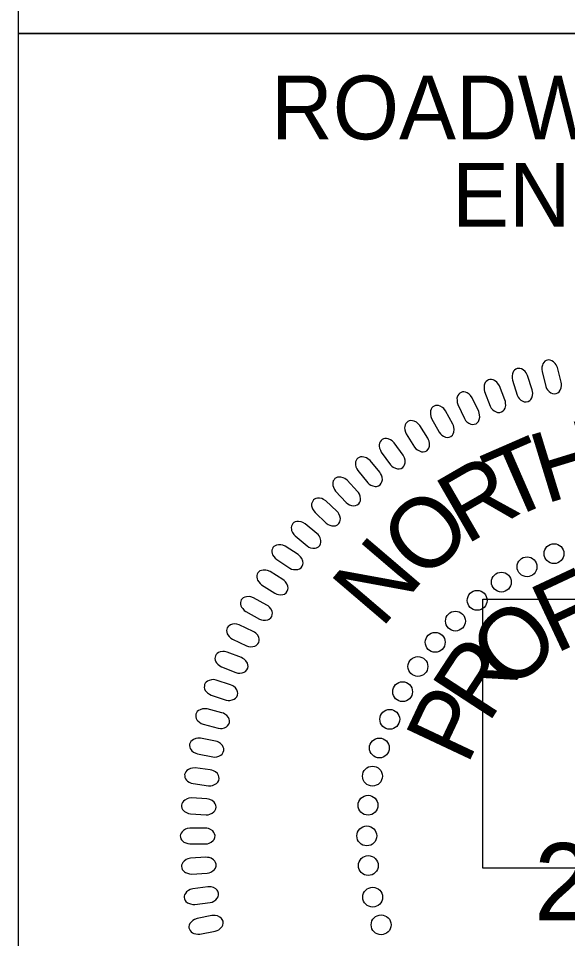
# Model space of a CAD drawing. Extents: x 18938 to 19565, y 6931 to 7973.
# Drawn here: x 19353.14 to 19358.89, y 7208.36 to 7218.01 of the extents above; entities that cross this region are included whole.
import ezdxf

# ---------------------------------------------------------------- set-up
doc = ezdxf.new("R2010")
doc.units = 0
for name, color, linetype in [('Old_Level_10', 7, 'Continuous'), ('Prop Pavement Schedule Description CELL', 7, 'Continuous'), ('Scratch_Level_5', 7, 'Continuous'), ('Typical Pavement Slope Information CELL', 7, 'Continuous')]:
    doc.layers.add(name, color=color, linetype=linetype)

# ---------------------------------------------------------------- blocks, each defined once
blk = doc.blocks.new('Brandon J. McInnis')
at = {"layer": 'Old_Level_10'}
for points in [[(-60.071, 87.604), (-60.375, 88.792), (-60.466, 88.995), (-60.552, 89.118), (-60.702, 89.254), (-60.824, 89.336), (-60.952, 89.386), (-61.064, 89.399), (-61.177, 89.39), (-61.281, 89.343), (-61.389, 89.284), (-61.476, 89.2), (-61.552, 89.077), (-61.591, 88.986), (-61.619, 88.823), (-61.632, 88.635), (-61.614, 88.475), (-61.309, 87.256), (-61.245, 87.097), (-61.167, 86.973), (-61.04, 86.841), (-60.897, 86.733), (-60.783, 86.681), (-60.616, 86.661), (-60.466, 86.679), (-60.331, 86.754), (-60.243, 86.829), (-60.144, 86.957), (-60.071, 87.151), (-60.05, 87.342), (-60.053, 87.474)], [(-62.405, 86.983), (-62.783, 88.15), (-62.886, 88.347), (-62.979, 88.464), (-63.138, 88.591), (-63.264, 88.665), (-63.396, 88.706), (-63.508, 88.712), (-63.62, 88.696), (-63.721, 88.643), (-63.825, 88.577), (-63.906, 88.489), (-63.975, 88.361), (-64.008, 88.266), (-64.026, 88.103), (-64.027, 87.914), (-63.999, 87.755), (-63.618, 86.558), (-63.544, 86.404), (-63.459, 86.285), (-63.324, 86.161), (-63.175, 86.063), (-63.058, 86.017), (-62.889, 86.008), (-62.741, 86.035), (-62.611, 86.119), (-62.527, 86.199), (-62.437, 86.333), (-62.376, 86.532), (-62.367, 86.723), (-62.379, 86.856)], [(-64.605, 86.167), (-65.057, 87.308), (-65.172, 87.498), (-65.272, 87.609), (-65.439, 87.725), (-65.569, 87.791), (-65.703, 87.824), (-65.815, 87.823), (-65.926, 87.8), (-66.023, 87.74), (-66.124, 87.668), (-66.199, 87.574), (-66.26, 87.443), (-66.286, 87.347), (-66.294, 87.183), (-66.283, 86.994), (-66.245, 86.838), (-65.79, 85.666), (-65.707, 85.517), (-65.614, 85.404), (-65.471, 85.288), (-65.316, 85.2), (-65.196, 85.161), (-65.028, 85.163), (-64.882, 85.2), (-64.758, 85.292), (-64.679, 85.377), (-64.597, 85.516), (-64.548, 85.718), (-64.552, 85.91), (-64.572, 86.041)], [(-66.723, 85.234), (-67.245, 86.344), (-67.372, 86.526), (-67.479, 86.631), (-67.652, 86.737), (-67.787, 86.794), (-67.922, 86.819), (-68.034, 86.811), (-68.144, 86.781), (-68.237, 86.715), (-68.332, 86.638), (-68.402, 86.539), (-68.454, 86.404), (-68.474, 86.306), (-68.472, 86.142), (-68.449, 85.954), (-68.402, 85.8), (-67.873, 84.661), (-67.781, 84.516), (-67.681, 84.409), (-67.532, 84.303), (-67.371, 84.224), (-67.25, 84.193), (-67.082, 84.206), (-66.938, 84.251), (-66.82, 84.351), (-66.746, 84.441), (-66.674, 84.585), (-66.637, 84.789), (-66.653, 84.98), (-66.681, 85.111)], [(-68.806, 84.22), (-69.397, 85.295), (-69.535, 85.47), (-69.648, 85.567), (-69.828, 85.662), (-69.966, 85.711), (-70.102, 85.727), (-70.213, 85.711), (-70.321, 85.675), (-70.41, 85.604), (-70.501, 85.52), (-70.563, 85.417), (-70.607, 85.279), (-70.621, 85.18), (-70.608, 85.017), (-70.574, 84.83), (-70.517, 84.68), (-69.918, 83.575), (-69.817, 83.437), (-69.71, 83.337), (-69.556, 83.24), (-69.389, 83.171), (-69.266, 83.148), (-69.099, 83.171), (-68.959, 83.226), (-68.847, 83.333), (-68.779, 83.427), (-68.716, 83.576), (-68.693, 83.782), (-68.72, 83.972), (-68.757, 84.099)], [(-70.823, 83.078), (-71.48, 84.114), (-71.63, 84.28), (-71.748, 84.369), (-71.933, 84.453), (-72.074, 84.493), (-72.211, 84.5), (-72.322, 84.478), (-72.427, 84.435), (-72.511, 84.358), (-72.596, 84.269), (-72.652, 84.162), (-72.687, 84.022), (-72.695, 83.923), (-72.672, 83.76), (-72.626, 83.577), (-72.56, 83.429), (-71.893, 82.364), (-71.783, 82.233), (-71.67, 82.139), (-71.509, 82.053), (-71.34, 81.995), (-71.215, 81.979), (-71.05, 82.013), (-70.914, 82.076), (-70.809, 82.19), (-70.747, 82.288), (-70.693, 82.44), (-70.683, 82.648), (-70.723, 82.836), (-70.766, 82.96)], [(-72.824, 81.723), (-73.545, 82.716), (-73.704, 82.872), (-73.828, 82.954), (-74.019, 83.026), (-74.162, 83.057), (-74.299, 83.056), (-74.408, 83.027), (-74.51, 82.977), (-74.589, 82.895), (-74.668, 82.801), (-74.717, 82.691), (-74.744, 82.548), (-74.745, 82.449), (-74.712, 82.288), (-74.655, 82.107), (-74.579, 81.965), (-73.847, 80.944), (-73.729, 80.82), (-73.611, 80.733), (-73.445, 80.657), (-73.272, 80.61), (-73.146, 80.602), (-72.984, 80.646), (-72.851, 80.718), (-72.754, 80.838), (-72.699, 80.939), (-72.654, 81.095), (-72.657, 81.303), (-72.708, 81.488), (-72.76, 81.61)], [(-74.704, 80.335), (-75.486, 81.28), (-75.655, 81.425), (-75.784, 81.5), (-75.978, 81.559), (-76.123, 81.582), (-76.26, 81.572), (-76.366, 81.535), (-76.465, 81.479), (-76.539, 81.392), (-76.612, 81.293), (-76.655, 81.181), (-76.672, 81.037), (-76.667, 80.937), (-76.624, 80.779), (-76.556, 80.603), (-76.471, 80.465), (-75.677, 79.492), (-75.551, 79.376), (-75.427, 79.297), (-75.257, 79.231), (-75.081, 79.195), (-74.955, 79.195), (-74.796, 79.249), (-74.668, 79.329), (-74.579, 79.455), (-74.53, 79.56), (-74.495, 79.718), (-74.512, 79.925), (-74.574, 80.106), (-74.634, 80.225)], [(-76.492, 78.795), (-77.331, 79.69), (-77.509, 79.825), (-77.643, 79.891), (-77.841, 79.938), (-77.986, 79.951), (-78.123, 79.933), (-78.226, 79.89), (-78.322, 79.828), (-78.39, 79.736), (-78.457, 79.632), (-78.492, 79.518), (-78.5, 79.373), (-78.489, 79.274), (-78.436, 79.119), (-78.356, 78.947), (-78.264, 78.816), (-77.409, 77.894), (-77.277, 77.786), (-77.149, 77.715), (-76.974, 77.66), (-76.796, 77.634), (-76.671, 77.642), (-76.516, 77.707), (-76.393, 77.795), (-76.312, 77.926), (-76.269, 78.034), (-76.244, 78.193), (-76.273, 78.399), (-76.348, 78.576), (-76.414, 78.691)], [(-78.154, 77.186), (-79.048, 78.026), (-79.234, 78.149), (-79.371, 78.207), (-79.572, 78.241), (-79.718, 78.246), (-79.853, 78.218), (-79.954, 78.169), (-80.045, 78.101), (-80.107, 78.006), (-80.167, 77.898), (-80.196, 77.782), (-80.195, 77.637), (-80.177, 77.538), (-80.115, 77.387), (-80.025, 77.22), (-79.924, 77.094), (-79.013, 76.229), (-78.874, 76.129), (-78.742, 76.066), (-78.564, 76.022), (-78.386, 76.009), (-78.261, 76.024), (-78.11, 76.098), (-77.993, 76.193), (-77.92, 76.33), (-77.884, 76.44), (-77.87, 76.601), (-77.911, 76.804), (-77.996, 76.976), (-78.07, 77.086)], [(-79.768, 75.399), (-80.712, 76.182), (-80.906, 76.293), (-81.046, 76.342), (-81.249, 76.363), (-81.395, 76.358), (-81.527, 76.323), (-81.625, 76.268), (-81.712, 76.194), (-81.768, 76.095), (-81.821, 75.983), (-81.843, 75.865), (-81.832, 75.721), (-81.809, 75.624), (-81.736, 75.477), (-81.636, 75.315), (-81.528, 75.197), (-80.565, 74.39), (-80.42, 74.299), (-80.284, 74.245), (-80.103, 74.212), (-79.925, 74.209), (-79.801, 74.234), (-79.655, 74.316), (-79.544, 74.418), (-79.479, 74.559), (-79.451, 74.671), (-79.447, 74.833), (-79.501, 75.033), (-79.596, 75.2), (-79.678, 75.305)], [(-81.292, 73.697), (-82.322, 74.363), (-82.527, 74.45), (-82.673, 74.483), (-82.876, 74.48), (-83.021, 74.458), (-83.148, 74.407), (-83.239, 74.341), (-83.317, 74.257), (-83.361, 74.153), (-83.4, 74.036), (-83.407, 73.916), (-83.38, 73.774), (-83.346, 73.68), (-83.256, 73.542), (-83.138, 73.394), (-83.016, 73.289), (-81.965, 72.601), (-81.81, 72.528), (-81.669, 72.49), (-81.486, 72.478), (-81.308, 72.497), (-81.188, 72.536), (-81.053, 72.635), (-80.955, 72.749), (-80.907, 72.897), (-80.892, 73.011), (-80.907, 73.172), (-80.984, 73.365), (-81.099, 73.519), (-81.192, 73.614)], [(-82.507, 71.674), (-83.542, 72.332), (-83.747, 72.418), (-83.893, 72.449), (-84.097, 72.446), (-84.241, 72.422), (-84.369, 72.37), (-84.458, 72.303), (-84.536, 72.219), (-84.579, 72.113), (-84.617, 71.997), (-84.623, 71.876), (-84.595, 71.735), (-84.56, 71.641), (-84.469, 71.504), (-84.35, 71.357), (-84.228, 71.253), (-83.17, 70.573), (-83.015, 70.501), (-82.873, 70.464), (-82.691, 70.454), (-82.513, 70.474), (-82.393, 70.513), (-82.259, 70.614), (-82.162, 70.73), (-82.115, 70.877), (-82.101, 70.992), (-82.117, 71.153), (-82.196, 71.344), (-82.312, 71.497), (-82.405, 71.593)], [(-83.81, 69.625), (-84.885, 70.217), (-85.095, 70.29), (-85.243, 70.311), (-85.445, 70.295), (-85.589, 70.262), (-85.712, 70.203), (-85.797, 70.13), (-85.869, 70.042), (-85.905, 69.934), (-85.937, 69.815), (-85.935, 69.694), (-85.898, 69.554), (-85.857, 69.464), (-85.759, 69.332), (-85.63, 69.193), (-85.501, 69.097), (-84.404, 68.485), (-84.245, 68.422), (-84.101, 68.395), (-83.918, 68.396), (-83.741, 68.427), (-83.624, 68.474), (-83.496, 68.582), (-83.407, 68.704), (-83.37, 68.854), (-83.363, 68.969), (-83.389, 69.129), (-83.48, 69.315), (-83.605, 69.461), (-83.704, 69.55)], [(-84.919, 67.501), (-86.029, 68.024), (-86.243, 68.084), (-86.392, 68.096), (-86.593, 68.067), (-86.734, 68.026), (-86.853, 67.958), (-86.934, 67.88), (-87, 67.787), (-87.03, 67.678), (-87.053, 67.556), (-87.044, 67.437), (-86.999, 67.3), (-86.952, 67.212), (-86.845, 67.087), (-86.708, 66.956), (-86.574, 66.867), (-85.439, 66.325), (-85.277, 66.274), (-85.131, 66.255), (-84.949, 66.268), (-84.775, 66.31), (-84.661, 66.364), (-84.54, 66.48), (-84.458, 66.607), (-84.431, 66.759), (-84.431, 66.876), (-84.467, 67.033), (-84.57, 67.213), (-84.703, 67.35), (-84.808, 67.433)], [(-85.858, 65.383), (-86.998, 65.834), (-87.216, 65.88), (-87.365, 65.884), (-87.565, 65.842), (-87.702, 65.792), (-87.817, 65.717), (-87.893, 65.634), (-87.953, 65.537), (-87.976, 65.426), (-87.992, 65.303), (-87.975, 65.184), (-87.921, 65.05), (-87.869, 64.965), (-87.754, 64.847), (-87.609, 64.726), (-87.47, 64.646), (-86.304, 64.176), (-86.139, 64.135), (-85.992, 64.125), (-85.811, 64.149), (-85.64, 64.202), (-85.529, 64.263), (-85.415, 64.387), (-85.343, 64.518), (-85.324, 64.672), (-85.332, 64.788), (-85.378, 64.943), (-85.492, 65.116), (-85.634, 65.245), (-85.744, 65.321)], [(-86.734, 63.193), (-87.901, 63.572), (-88.121, 63.605), (-88.27, 63.599), (-88.466, 63.545), (-88.601, 63.486), (-88.711, 63.404), (-88.781, 63.317), (-88.834, 63.216), (-88.85, 63.103), (-88.859, 62.98), (-88.834, 62.863), (-88.772, 62.732), (-88.714, 62.65), (-88.593, 62.54), (-88.441, 62.428), (-88.296, 62.357), (-87.103, 61.961), (-86.935, 61.93), (-86.788, 61.93), (-86.609, 61.966), (-86.442, 62.029), (-86.335, 62.097), (-86.23, 62.227), (-86.165, 62.363), (-86.157, 62.518), (-86.172, 62.633), (-86.227, 62.785), (-86.351, 62.951), (-86.502, 63.07), (-86.616, 63.139)], [(-87.438, 60.938), (-88.627, 61.243), (-88.848, 61.261), (-88.997, 61.246), (-89.189, 61.179), (-89.319, 61.113), (-89.425, 61.024), (-89.489, 60.932), (-89.537, 60.829), (-89.545, 60.716), (-89.546, 60.592), (-89.514, 60.475), (-89.444, 60.35), (-89.381, 60.272), (-89.253, 60.169), (-89.094, 60.067), (-88.945, 60.005), (-87.73, 59.685), (-87.56, 59.665), (-87.414, 59.673), (-87.237, 59.721), (-87.074, 59.794), (-86.972, 59.868), (-86.875, 60.006), (-86.819, 60.146), (-86.82, 60.3), (-86.842, 60.414), (-86.907, 60.562), (-87.041, 60.72), (-87.199, 60.83), (-87.317, 60.891)], [(-87.95, 58.642), (-89.154, 58.872), (-89.377, 58.877), (-89.524, 58.852), (-89.712, 58.773), (-89.838, 58.699), (-89.937, 58.603), (-89.996, 58.508), (-90.037, 58.402), (-90.038, 58.288), (-90.031, 58.165), (-89.992, 58.051), (-89.914, 57.929), (-89.847, 57.856), (-89.712, 57.761), (-89.547, 57.669), (-89.395, 57.617), (-88.161, 57.373), (-87.991, 57.364), (-87.845, 57.382), (-87.672, 57.44), (-87.514, 57.524), (-87.417, 57.604), (-87.329, 57.747), (-87.281, 57.891), (-87.292, 58.045), (-87.322, 58.157), (-87.396, 58.301), (-87.539, 58.45), (-87.704, 58.55), (-87.826, 58.603)], [(-88.37, 56.328), (-89.587, 56.482), (-89.809, 56.472), (-89.955, 56.438), (-90.137, 56.348), (-90.258, 56.266), (-90.351, 56.164), (-90.404, 56.066), (-90.438, 55.957), (-90.432, 55.843), (-90.417, 55.72), (-90.371, 55.609), (-90.285, 55.493), (-90.214, 55.424), (-90.074, 55.338), (-89.903, 55.256), (-89.748, 55.214), (-88.502, 55.048), (-88.331, 55.05), (-88.187, 55.077), (-88.018, 55.145), (-87.865, 55.239), (-87.774, 55.326), (-87.694, 55.474), (-87.655, 55.62), (-87.677, 55.773), (-87.713, 55.883), (-87.796, 56.022), (-87.949, 56.161), (-88.119, 56.251), (-88.243, 56.297)], [(-88.656, 53.984), (-89.881, 54.061), (-90.102, 54.038), (-90.245, 53.994), (-90.421, 53.893), (-90.537, 53.803), (-90.624, 53.696), (-90.67, 53.594), (-90.697, 53.484), (-90.684, 53.371), (-90.661, 53.249), (-90.609, 53.141), (-90.516, 53.031), (-90.44, 52.966), (-90.295, 52.889), (-90.12, 52.818), (-89.962, 52.786), (-88.708, 52.699), (-88.537, 52.71), (-88.395, 52.746), (-88.23, 52.826), (-88.084, 52.929), (-87.998, 53.021), (-87.929, 53.174), (-87.899, 53.322), (-87.93, 53.473), (-87.973, 53.581), (-88.064, 53.714), (-88.226, 53.844), (-88.401, 53.923), (-88.528, 53.96)], [(-88.787, 51.633), (-90.013, 51.633), (-90.233, 51.595), (-90.373, 51.544), (-90.542, 51.432), (-90.652, 51.334), (-90.731, 51.222), (-90.771, 51.118), (-90.792, 51.005), (-90.771, 50.894), (-90.742, 50.774), (-90.682, 50.669), (-90.582, 50.565), (-90.503, 50.505), (-90.353, 50.437), (-90.173, 50.378), (-90.014, 50.355), (-88.757, 50.347), (-88.588, 50.369), (-88.448, 50.415), (-88.289, 50.504), (-88.149, 50.616), (-88.069, 50.713), (-88.009, 50.87), (-87.989, 51.02), (-88.029, 51.169), (-88.079, 51.274), (-88.178, 51.401), (-88.348, 51.521), (-88.527, 51.588), (-88.657, 51.618)], [(-88.734, 49.275), (-89.959, 49.199), (-90.175, 49.148), (-90.311, 49.087), (-90.474, 48.964), (-90.578, 48.86), (-90.65, 48.743), (-90.683, 48.637), (-90.696, 48.523), (-90.669, 48.413), (-90.631, 48.295), (-90.566, 48.195), (-90.459, 48.096), (-90.376, 48.042), (-90.222, 47.984), (-90.039, 47.936), (-89.879, 47.923), (-88.624, 47.994), (-88.456, 48.027), (-88.32, 48.081), (-88.166, 48.181), (-88.034, 48.301), (-87.96, 48.402), (-87.91, 48.563), (-87.9, 48.713), (-87.949, 48.86), (-88.005, 48.962), (-88.113, 49.082), (-88.289, 49.191), (-88.473, 49.247), (-88.604, 49.269)], [(-88.569, 46.894), (-89.787, 46.741), (-89.999, 46.676), (-90.132, 46.607), (-90.286, 46.475), (-90.383, 46.364), (-90.448, 46.243), (-90.474, 46.134), (-90.48, 46.02), (-90.446, 45.912), (-90.402, 45.797), (-90.33, 45.7), (-90.217, 45.609), (-90.13, 45.56), (-89.974, 45.512), (-89.788, 45.475), (-89.627, 45.473), (-88.379, 45.622), (-88.214, 45.665), (-88.081, 45.728), (-87.934, 45.836), (-87.809, 45.965), (-87.742, 46.071), (-87.702, 46.235), (-87.702, 46.386), (-87.76, 46.529), (-87.822, 46.627), (-87.937, 46.741), (-88.12, 46.838), (-88.307, 46.882), (-88.439, 46.895)], [(-88.236, 44.569), (-89.441, 44.339), (-89.65, 44.261), (-89.777, 44.185), (-89.923, 44.042), (-90.013, 43.926), (-90.07, 43.801), (-90.089, 43.691), (-90.088, 43.577), (-90.047, 43.471), (-89.995, 43.359), (-89.918, 43.267), (-89.8, 43.183), (-89.71, 43.139), (-89.55, 43.101), (-89.363, 43.076), (-89.202, 43.083), (-87.966, 43.311), (-87.804, 43.365), (-87.675, 43.435), (-87.536, 43.553), (-87.419, 43.69), (-87.359, 43.8), (-87.33, 43.965), (-87.338, 44.116), (-87.405, 44.255), (-87.473, 44.349), (-87.595, 44.455), (-87.784, 44.541), (-87.974, 44.573), (-88.106, 44.578)]]:
    blk.add_lwpolyline(points, close=True, dxfattribs=at)
for centre in [(-60.65, 73.77), (-62.825, 72.709), (-64.895, 71.475), (-66.847, 70.001), (-68.599, 68.329), (-70.232, 66.616), (-71.626, 64.665), (-72.861, 62.633), (-73.897, 60.403), (-74.734, 58.093), (-75.292, 55.822), (-75.651, 53.472), (-75.748, 50.997), (-75.629, 48.607), (-75.271, 46.057), (-74.595, 43.826)]:
    blk.add_circle(centre, 0.801, dxfattribs=at)
for s, height, rotation, p in [('H', 5.669, 17.05575, (-61.361, 77.767)), ('T', 5.669, 23.5451, (-64.54, 76.357)), ('R', 5.669, 30.03446, (-67.761, 74.438)), ('O', 5.669, 43.01317, (-71.236, 71.41)), ('N', 5.669, 49.50253, (-74.583, 67.655)), ('F', 5.669, 25.10842, (-60.555, 65.659)), ('O', 5.669, 40.98802, (-64.252, 62.521)), ('R', 5.669, 56.86761, (-65.966, 59.974)), ('P', 5.669, 64.80741, (-67.652, 56.612)), ('29470', 6.2363, 359.98136, (-62.253, 44.185))]:
    blk.add_text(s, height=height, rotation=rotation, dxfattribs=at).set_placement(p)

msp = doc.modelspace()

# ---------------------------------------------------------------- linework, layer by layer
at = {"layer": 'Scratch_Level_5'}
msp.add_lwpolyline([(19358.0043, 7209.0943), (19358.0043, 7211.9143), (19375.6443, 7211.9143), (19375.6443, 7209.0943)], close=True, dxfattribs=at)
at = {"layer": 'Typical Pavement Slope Information CELL'}
for points in [[(19353.1353, 7221.1971), (19380.142, 7221.1971), (19380.142, 7217.8472), (19353.1353, 7217.8472)], [(19353.1353, 7217.8472), (19366.642, 7217.8472), (19366.642, 7202.8026), (19353.1353, 7202.8026)]]:
    msp.add_lwpolyline(points, close=True, dxfattribs=at)

# ---------------------------------------------------------------- block references
at = {"layer": 'Prop Pavement Schedule Description CELL', "xscale": 0.13, "yscale": 0.13}
msp.add_blockref('Brandon J. McInnis', (19366.6353, 7202.8026), dxfattribs=at)

# ---------------------------------------------------------------- texts
at = {"layer": 'Typical Pavement Slope Information CELL'}
for s, height, p in [('ROADWAY DESIGN', 0.668659, (19355.7854, 7216.7374)), ('ENGINEER', 0.66866, (19357.6821, 7215.8214))]:
    msp.add_text(s, height=height, dxfattribs=at).set_placement(p)

doc.saveas('drawing.dxf')
